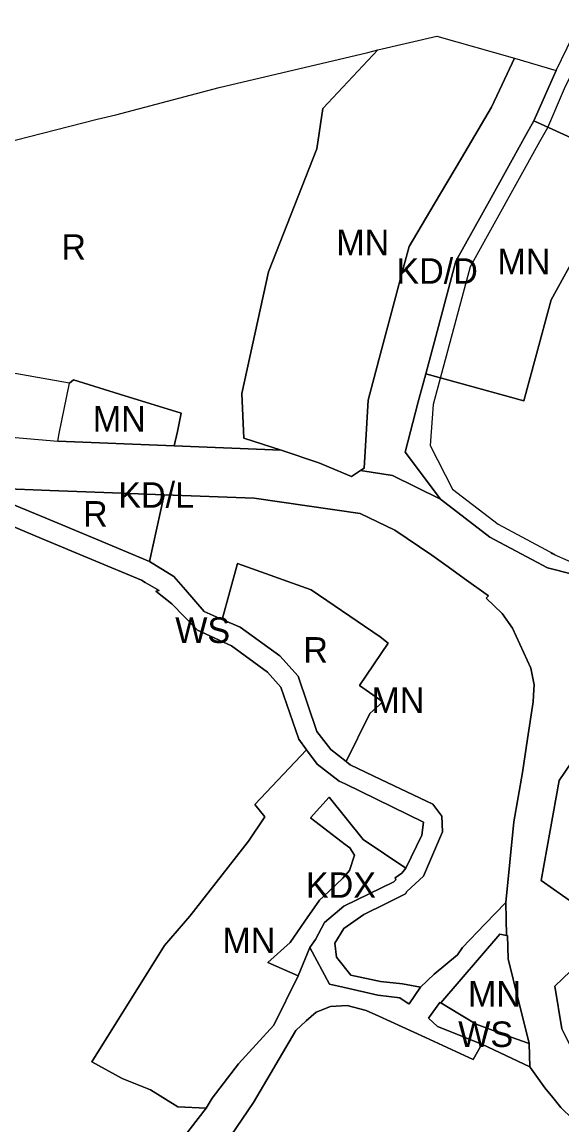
# Model space of a CAD drawing. Extents: x 7438199 to 7440548, y 5549253 to 5551017.
# Drawn here: x 7438705.9 to 7438917.7, y 5550359.8 to 5550792.4 of the extents above; entities that cross this region are included whole.
import ezdxf

# ---------------------------------------------------------------- set-up
doc = ezdxf.new("R2010")
doc.units = 0
for name, color, linetype in [('linie_rozgraniczajace', 7, 'Continuous'), ('linie_zabudowy_nieprzekraczalne', 7, 'Continuous'), ('oznaczenia_przeznaczen', 7, 'Continuous')]:
    doc.layers.add(name, color=color, linetype=linetype)

msp = doc.modelspace()

# ---------------------------------------------------------------- linework, layer by layer
at = {"layer": 'linie_rozgraniczajace'}
for points in [[(7438906.66, 5550753.65), (7438915.42, 5550773.41), (7438930.38, 5550804.29), (7438991.1, 5550818.07), (7439026, 5550825.99), (7439042.73, 5550830.95), (7439048.59, 5550832.62), (7439095.81, 5550842.97), (7439096.81, 5550837.3), (7439096, 5550833.11), (7439095.84, 5550832.32), (7439096.59, 5550828.7), (7439092.49, 5550816.41), (7439050.34, 5550699.54), (7439048.59, 5550694.66), (7439046.85, 5550689.8), (7439020.82, 5550701.66), (7438943.17, 5550737.02)], [(7438792.08, 5550646.72), (7438802.64, 5550694.47), (7438821.61, 5550742.72), (7438823.94, 5550758.49), (7438845.47, 5550781.45), (7438868.57, 5550786.91), (7438899.05, 5550778.19), (7438894.27, 5550767.94), (7438890.12, 5550759.06), (7438878.28, 5550739.07), (7438867.58, 5550720.99), (7438857.73, 5550704.36), (7438855.07, 5550694.34), (7438852.53, 5550684.84), (7438845.89, 5550659.96), (7438841.65, 5550644.06), (7438840.62, 5550626.23), (7438840.13, 5550617.45), (7438838.67, 5550616.49), (7438835.17, 5550614.2), (7438822.38, 5550619.46), (7438807.63, 5550624.46), (7438792.95, 5550629.24)], [(7438838.67, 5550616.49), (7438840.13, 5550617.45), (7438840.62, 5550626.23), (7438841.65, 5550644.06), (7438845.89, 5550659.96), (7438852.53, 5550684.84), (7438855.07, 5550694.34), (7438857.73, 5550704.36), (7438867.58, 5550720.99), (7438878.28, 5550739.07), (7438890.12, 5550759.06), (7438894.27, 5550767.94), (7438899.05, 5550778.19), (7438915.42, 5550773.41), (7438906.66, 5550753.65), (7438903.68, 5550748.28), (7438889.91, 5550723.46), (7438876.14, 5550698.63), (7438868.71, 5550671.05), (7438864.25, 5550654.48), (7438861.28, 5550643.47), (7438856.2, 5550623.73), (7438870.1, 5550605.3), (7438851.3, 5550614.57)], [(7438864.25, 5550654.48), (7438868.71, 5550671.05), (7438876.14, 5550698.63), (7438889.91, 5550723.46), (7438903.68, 5550748.28), (7438906.66, 5550753.65), (7438943.17, 5550737.02), (7438938.66, 5550728.88), (7438924.89, 5550704.05), (7438913.49, 5550683.5), (7438907.33, 5550660.65), (7438902.8, 5550643.82)], [(7438856.2, 5550623.73), (7438861.28, 5550643.47), (7438864.25, 5550654.48), (7438902.8, 5550643.82), (7438907.33, 5550660.65), (7438913.49, 5550683.5), (7438924.89, 5550704.05), (7438938.66, 5550728.88), (7438943.17, 5550737.02), (7439020.82, 5550701.66), (7439014.6, 5550684.53), (7438983.31, 5550598.22), (7438970.07, 5550565.25), (7438966.11, 5550565.02), (7438954.64, 5550567.5), (7438928.95, 5550577.22), (7438927.29, 5550573.44), (7438921.86, 5550575.86), (7438912.06, 5550578.32), (7438889.4, 5550590.35), (7438870.1, 5550605.3)], [(7438719.92, 5550628.01), (7438720.53, 5550630.99), (7438724.59, 5550650.73), (7438726.09, 5550652.13), (7438744.16, 5550646.49), (7438768.4, 5550638.99), (7438766.94, 5550631.82), (7438765.62, 5550626.16)], [(7438671.7, 5550610.37), (7438696.99, 5550609.45), (7438716.87, 5550608.71), (7438737.96, 5550607.87), (7438761.69, 5550606.92), (7438755.95, 5550580.78), (7438734.69, 5550589.67), (7438714.95, 5550597.94), (7438697.63, 5550605.18), (7438696.25, 5550605.39)], [(7438755.95, 5550580.78), (7438761.69, 5550606.92), (7438797, 5550605.68), (7438838.54, 5550599.62), (7438852.19, 5550593.13), (7438866.73, 5550583.23), (7438873.06, 5550578.68), (7438879.39, 5550574.14), (7438888.89, 5550567.32), (7438887.92, 5550566.48), (7438894.22, 5550560.43), (7438898.26, 5550554.64), (7438905.55, 5550538.97), (7438906.82, 5550532.42), (7438906.48, 5550528.4), (7438906.44, 5550525.8), (7438904.14, 5550511.19), (7438902.26, 5550498.06), (7438898.89, 5550478.66), (7438895.66, 5550447.04), (7438887.5, 5550438.54), (7438878.73, 5550429.38), (7438876.68, 5550426.46), (7438867.55, 5550418.91), (7438862.27, 5550413.79), (7438855.11, 5550415.14), (7438846.54, 5550416.04), (7438834.84, 5550418.57), (7438829.28, 5550425.62), (7438828.68, 5550431.1), (7438832.09, 5550436.81), (7438839.98, 5550442.3), (7438848.72, 5550446.65), (7438855.32, 5550449.92), (7438856.4, 5550450.51), (7438856.9, 5550451.35), (7438863.34, 5550457.44), (7438870.88, 5550474.73), (7438870.64, 5550480.86), (7438867.07, 5550485.56), (7438846.68, 5550495.35), (7438834.68, 5550501.1), (7438833.23, 5550502.22), (7438833.05, 5550502.36), (7438842.34, 5550521.21), (7438847.49, 5550525.76), (7438838.24, 5550532.17), (7438849.48, 5550548.75), (7438846.41, 5550551.26), (7438819.34, 5550569.7), (7438790.45, 5550580.09), (7438784.4, 5550558.02), (7438777.38, 5550561.2), (7438770.03, 5550569.7), (7438765.51, 5550574.91)], [(7438784.4, 5550558.02), (7438790.45, 5550580.09), (7438819.34, 5550569.7), (7438846.41, 5550551.26), (7438849.48, 5550548.75), (7438838.24, 5550532.17), (7438847.49, 5550525.76), (7438842.34, 5550521.21), (7438833.05, 5550502.36), (7438827.01, 5550507.02), (7438821.62, 5550514.11), (7438814.24, 5550535.77), (7438807.08, 5550543.81), (7438791.46, 5550555.02)], [(7438909.55, 5550455.66), (7438916.57, 5550494.9), (7438926.49, 5550509.6), (7438926.58, 5550511), (7438938.54, 5550507.28), (7438967.77, 5550497.26), (7438970.36, 5550489.69), (7438965.51, 5550479.19), (7438964.49, 5550476.99), (7438962.44, 5550473.61), (7438944.88, 5550444.76), (7438937.38, 5550438.78), (7438933.68, 5550438.7)], [(7438733.35, 5550384.6), (7438761.85, 5550430.25), (7438771.79, 5550441.65), (7438794.76, 5550471.05), (7438801.12, 5550480.69), (7438797.24, 5550485.48), (7438817.5, 5550506.95), (7438821.67, 5550501.34), (7438830.28, 5550494.66), (7438832.65, 5550493.56), (7438863.39, 5550478.57), (7438862.76, 5550473.49), (7438856.45, 5550460.46), (7438839.73, 5550471.8), (7438826.42, 5550488.33), (7438819.02, 5550480.32), (7438832.72, 5550469.75), (7438834.56, 5550468.44), (7438836.33, 5550465.62), (7438834.35, 5550459.58), (7438831.74, 5550456.62), (7438824.16, 5550449.47), (7438822.63, 5550448.01), (7438816.84, 5550439.69), (7438811.05, 5550431.37), (7438802.36, 5550423.5), (7438814.23, 5550418.28), (7438804.66, 5550398.94), (7438790.82, 5550383.74), (7438780.54, 5550370.24), (7438778.11, 5550366.38), (7438767, 5550366.96), (7438756.29, 5550373.57), (7438745.24, 5550378.07)], [(7438802.36, 5550423.5), (7438811.05, 5550431.37), (7438816.84, 5550439.69), (7438822.63, 5550448.01), (7438824.16, 5550449.47), (7438831.74, 5550456.62), (7438834.35, 5550459.58), (7438836.33, 5550465.62), (7438834.56, 5550468.44), (7438832.72, 5550469.75), (7438819.02, 5550480.32), (7438826.42, 5550488.33), (7438839.73, 5550471.8), (7438856.45, 5550460.46), (7438854.92, 5550458.59), (7438852.3, 5550456.74), (7438852.6, 5550455.99), (7438851.78, 5550455.21), (7438832.1, 5550445.64), (7438824.58, 5550439.18), (7438821.06, 5550432.52), (7438818.85, 5550429.41), (7438814.23, 5550418.28)], [(7438870.22, 5550407.68), (7438893.37, 5550434.58), (7438895.93, 5550434.08), (7438896.35, 5550434.12), (7438896.57, 5550425.02), (7438900.69, 5550408.48), (7438904.81, 5550391.93), (7438904.82, 5550391.79), (7438904.1, 5550391.96), (7438896.34, 5550394.78), (7438884.07, 5550399.35), (7438877.49, 5550403.22)], [(7438914.85, 5550414.19), (7438927.18, 5550426), (7438934.63, 5550426.93), (7438942.08, 5550427.87), (7438949.38, 5550422.2), (7438959.12, 5550411.62), (7438989.51, 5550376.09), (7438975.32, 5550370.81), (7438959.14, 5550360.57), (7438951.8, 5550360.38), (7438931.15, 5550379.14), (7438924.31, 5550384.19), (7438917.65, 5550397.54)], [(7438865.35, 5550401.73), (7438869.84, 5550407.88), (7438870.22, 5550407.68), (7438877.49, 5550403.22), (7438884.07, 5550399.35), (7438896.34, 5550394.78), (7438904.1, 5550391.96), (7438904.82, 5550391.79), (7438905.07, 5550382.61), (7438886.22, 5550391.53), (7438868.92, 5550398.36)]]:
    msp.add_lwpolyline(points, close=True, dxfattribs=at)
for points in [[(7438634.69, 5550728.62), (7438713.89, 5550748.85), (7438735.39, 5550754.35), (7438742.78, 5550756.08), (7438783.21, 5550766.74), (7438841.5, 5550780.51), (7438845.47, 5550781.45), (7438823.94, 5550758.49), (7438821.61, 5550742.72), (7438802.64, 5550694.47), (7438792.08, 5550646.72), (7438792.95, 5550629.24), (7438807.63, 5550624.46), (7438765.62, 5550626.16), (7438766.94, 5550631.82), (7438768.4, 5550638.99), (7438744.16, 5550646.49), (7438726.09, 5550652.13), (7438724.59, 5550650.73), (7438695.64, 5550655.89)], [(7438631.96, 5550635.63), (7438719.92, 5550628.01), (7438765.62, 5550626.16), (7438807.63, 5550624.46), (7438822.38, 5550619.46), (7438835.17, 5550614.2), (7438838.67, 5550616.49), (7438851.3, 5550614.57), (7438870.1, 5550605.3), (7438889.4, 5550590.35), (7438912.06, 5550578.32), (7438921.86, 5550575.86)], [(7438894.22, 5550560.43), (7438887.92, 5550566.48), (7438888.89, 5550567.32), (7438879.39, 5550574.14), (7438873.06, 5550578.68), (7438866.73, 5550583.23), (7438852.19, 5550593.13), (7438838.54, 5550599.62), (7438797, 5550605.68), (7438761.69, 5550606.92), (7438737.96, 5550607.87), (7438716.87, 5550608.71), (7438696.99, 5550609.45), (7438671.7, 5550610.37), (7438600.01, 5550613.25), (7438573.42, 5550615.16), (7438549.07, 5550616.55), (7438519.34, 5550618.2), (7438489.33, 5550619.92), (7438385.44, 5550620.39), (7438338.91, 5550620.88), (7438296.06, 5550614.59), (7438265.38, 5550607.05)], [(7438697.63, 5550605.18), (7438714.95, 5550597.94), (7438734.69, 5550589.67), (7438755.95, 5550580.78), (7438765.51, 5550574.91), (7438770.03, 5550569.7), (7438777.38, 5550561.2), (7438784.4, 5550558.02), (7438791.46, 5550555.02), (7438807.08, 5550543.81), (7438814.24, 5550535.77), (7438821.62, 5550514.11), (7438827.01, 5550507.02), (7438833.05, 5550502.36), (7438833.23, 5550502.22), (7438834.68, 5550501.1), (7438846.68, 5550495.35), (7438867.07, 5550485.56), (7438870.64, 5550480.86), (7438870.88, 5550474.73), (7438863.34, 5550457.44), (7438856.9, 5550451.35), (7438856.4, 5550450.51), (7438855.32, 5550449.92), (7438848.72, 5550446.65), (7438839.98, 5550442.3), (7438832.09, 5550436.81), (7438828.68, 5550431.1), (7438829.28, 5550425.62), (7438834.84, 5550418.57), (7438846.54, 5550416.04), (7438855.11, 5550415.14), (7438862.27, 5550413.79), (7438857.75, 5550407.26), (7438857.64, 5550407.34), (7438857.43, 5550407.37), (7438854.18, 5550409.62), (7438845.51, 5550410.68), (7438832.41, 5550413.71), (7438826.48, 5550415.08), (7438818.85, 5550429.41), (7438821.06, 5550432.52), (7438824.58, 5550439.18), (7438832.1, 5550445.64), (7438851.78, 5550455.21), (7438852.6, 5550455.99), (7438852.3, 5550456.74), (7438854.92, 5550458.59), (7438856.45, 5550460.46), (7438862.76, 5550473.49), (7438863.39, 5550478.57), (7438832.65, 5550493.56), (7438830.28, 5550494.66), (7438821.67, 5550501.34), (7438817.5, 5550506.95), (7438814.46, 5550511.06), (7438807.44, 5550531.51), (7438802.18, 5550537.44), (7438788.08, 5550547.75), (7438774.8, 5550553.86), (7438764.66, 5550564.26), (7438758.39, 5550569.23), (7438759.72, 5550569.42), (7438754.16, 5550572.58), (7438752.8, 5550573.49), (7438733.24, 5550581.65), (7438713.52, 5550589.86), (7438694.83, 5550597.65)], [(7438694.83, 5550597.65), (7438713.52, 5550589.86), (7438733.24, 5550581.65), (7438752.8, 5550573.49), (7438754.16, 5550572.58), (7438759.72, 5550569.42), (7438758.39, 5550569.23), (7438764.66, 5550564.26), (7438774.8, 5550553.86), (7438788.08, 5550547.75), (7438802.18, 5550537.44), (7438807.44, 5550531.51), (7438814.46, 5550511.06), (7438817.5, 5550506.95), (7438797.24, 5550485.48), (7438801.12, 5550480.69), (7438794.76, 5550471.05), (7438771.79, 5550441.65), (7438761.85, 5550430.25), (7438733.35, 5550384.6), (7438745.24, 5550378.07), (7438756.29, 5550373.57), (7438767, 5550366.96), (7438778.11, 5550366.38), (7438765.62, 5550350.13)], [(7438926.4, 5550357.75), (7438917.29, 5550366.61), (7438914.15, 5550370.51), (7438911.03, 5550374.37), (7438905.07, 5550382.61), (7438904.82, 5550391.79), (7438904.81, 5550391.93), (7438900.69, 5550408.48), (7438896.57, 5550425.02), (7438896.35, 5550434.12), (7438895.93, 5550434.08), (7438895.8, 5550440.56), (7438895.66, 5550447.04), (7438898.89, 5550478.66), (7438902.26, 5550498.06), (7438904.14, 5550511.19), (7438906.44, 5550525.8), (7438906.48, 5550528.4), (7438906.82, 5550532.42), (7438905.55, 5550538.97), (7438898.26, 5550554.64), (7438894.22, 5550560.43)], [(7438926.49, 5550509.6), (7438916.57, 5550494.9), (7438909.55, 5550455.66), (7438933.68, 5550438.7)], [(7438765.62, 5550350.13), (7438778.11, 5550366.38), (7438780.54, 5550370.24), (7438790.82, 5550383.74), (7438804.66, 5550398.94), (7438814.23, 5550418.28), (7438818.85, 5550429.41), (7438826.48, 5550415.08), (7438832.41, 5550413.71), (7438845.51, 5550410.68), (7438854.18, 5550409.62), (7438857.43, 5550407.37), (7438857.64, 5550407.34), (7438857.75, 5550407.26), (7438862.27, 5550413.79), (7438867.55, 5550418.91), (7438876.68, 5550426.46), (7438878.73, 5550429.38), (7438887.5, 5550438.54), (7438895.66, 5550447.04), (7438895.8, 5550440.56), (7438895.93, 5550434.08), (7438893.37, 5550434.58), (7438870.22, 5550407.68), (7438869.84, 5550407.88), (7438865.35, 5550401.73), (7438868.92, 5550398.36), (7438886.22, 5550391.53), (7438882.86, 5550385.45), (7438864.2, 5550394.06), (7438845.84, 5550402.45), (7438840.95, 5550404.64), (7438833.47, 5550406.62), (7438826.88, 5550406.22), (7438821.33, 5550404.09), (7438817.34, 5550400.58), (7438813.34, 5550396.85), (7438796.75, 5550368.59), (7438787.79, 5550355.53)], [(7438927.18, 5550426), (7438914.85, 5550414.19), (7438917.65, 5550397.54), (7438924.31, 5550384.19)], [(7438787.79, 5550355.53), (7438796.75, 5550368.59), (7438813.34, 5550396.85), (7438817.34, 5550400.58), (7438821.33, 5550404.09), (7438826.88, 5550406.22), (7438833.47, 5550406.62), (7438840.95, 5550404.64), (7438845.84, 5550402.45), (7438864.2, 5550394.06), (7438882.86, 5550385.45), (7438886.22, 5550391.53), (7438905.07, 5550382.61), (7438911.03, 5550374.37), (7438914.15, 5550370.51), (7438917.29, 5550366.61), (7438926.4, 5550357.75)]]:
    msp.add_lwpolyline(points, dxfattribs=at)
at = {"layer": 'linie_zabudowy_nieprzekraczalne'}
msp.add_lwpolyline([(7439095.37, 5550829.88), (7439051.74, 5550820.31), (7439029.48, 5550813.78), (7438992.26, 5550805.31), (7438930.79, 5550791.35), (7438918.61, 5550766.23), (7438912.04, 5550750.97), (7438908.93, 5550745.37), (7438881.74, 5550696.36), (7438867.22, 5550642.45), (7438866, 5550626.32), (7438874.82, 5550609.23), (7438892.67, 5550595.4), (7438914.88, 5550583.61), (7438913.52, 5550584.14), (7438928.95, 5550577.22)], dxfattribs=at)

# ---------------------------------------------------------------- texts
at = {"layer": 'oznaczenia_przeznaczen'}
for s, p in [('R', (7438721.37, 5550699.14)), ('MN', (7438829.17, 5550700.93)), ('KD/D', (7438852.77, 5550689.77)), ('MN', (7438892.38, 5550693.47)), ('MN', (7438733.67, 5550631.79)), ('KD/L', (7438743.66, 5550601.92)), ('R', (7438729.87, 5550594.49)), ('WS', (7438766.02, 5550548.86)), ('R', (7438816.27, 5550541.13)), ('MN', (7438842.97, 5550521.43)), ('KDX', (7438817.29, 5550448.91)), ('MN', (7438784.52, 5550427.19)), ('MN', (7438880.83, 5550406.23)), ('WS', (7438877.02, 5550390.38))]:
    msp.add_text(s, height=10, dxfattribs=at).set_placement(p)

doc.saveas('drawing.dxf')
